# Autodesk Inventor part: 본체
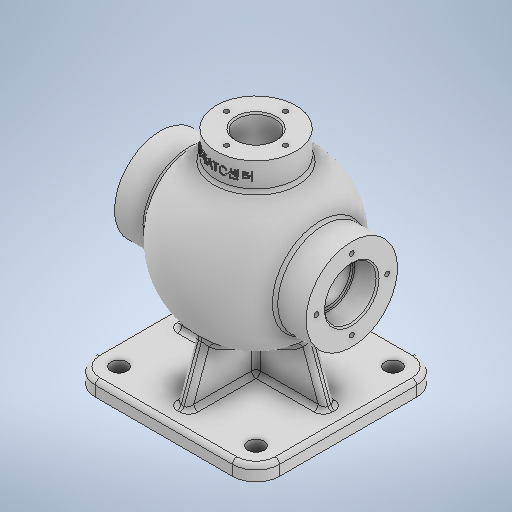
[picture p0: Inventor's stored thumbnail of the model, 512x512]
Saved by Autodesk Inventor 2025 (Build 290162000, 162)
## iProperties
Created: 2024-07
Part Number: 본체
Material: 일반
Document SubType Name: Modeling
Designer: song
Density: 1 g/cm^3
Appearance: 기본값
Mass: 566.359 g
Surface Area: 1179.94 cm^2
Volume: 566.359 cm^3
Author: song
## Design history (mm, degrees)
sketch "스케치1"
  geometry: L1 (-62.5, 62.5)-(62.5, 62.5); L2 (62.5, 62.5)-(62.5, -62.5); L3 (62.5, -62.5)-(-62.5, -62.5); L4 (-62.5, -62.5)-(-62.5, 62.5); L5 (-62.5, 62.5)-(62.5, -62.5); L6 (62.5, 62.5)-(-62.5, -62.5); 1 further point
  constraints: 12 end point, 2 midpoint, 2 parallel, 1 horizontal, 1 perpendicular
  dimensions: "d0" = 125 distance of L2.end L3.end; "d1" = 125 distance of L3.end L1.start
extrude "돌출1" new body sketch "스케치1" distance "d2" = 10; taper "d3" = 0 deg
sketch "스케치2"
  geometry: L1 (-62.5, 0)-(62.5, 0) reference; L2 (-65, 85)-(117.341, 85); L3 (-65, 85)-(-65, 116); L4 (-65, 116)-(-44.215, 116); L5 (65, 85)-(65, 116); L6 (65, 116)-(44.215, 116); L7 (0, 154.371)-(0, -36.93); A1 r 54 centre (0, 85) between (44.215, 116) and (-44.215, 116); 2 further points
  constraints: 12 end point, 3 point on line, 3 vertical, 2 perpendicular, 2 point on circle, 1 centre point, 1 horizontal, 1 midpoint, 1 vertical alignment, 1 other
  dimensions: "d5" = 85 distance between parallel lines of L1 L2; "d6" = 31 distance between parallel lines of L2 L4; "d7" = 65 distance from line of A1.centre L3; "d8" = 31 distance between parallel lines of L2 L6; "d9" = 54 radius of A1
revolve "회전1" sketch "스케치2" stored, may be unused: angle "d10" = 90 deg
node "작업 평면1"
sketch "스케치3"
  geometry: C1 r 27 at (0, 0); 1 further point
  constraints: 1 centre point, 1 coincident
  dimensions: "d12" = 54 diameter of C1
extrude "돌출2" join sketch "스케치3" stored distance "d13" = 10; taper "d14" = 0 deg
sketch "스케치4"
  geometry: L1 (-32.301, 60)-(-50.5, 10); L2 (62.5, 10)-(-62.5, 10) reference; L3 (-62.5, 0)-(-62.5, 10) reference; L4 (-50.5, 10)-(50.5, 10); L5 (50.5, 10)-(32.301, 60); L6 (62.5, 0)-(62.5, 10) reference; L7 (-32.301, 60)-(32.301, 60); A1 r 54 centre (0, 85) between (-44.215, 54) and (-44.215, 116) reference; 1 further point
  constraints: 8 end point, 1 collinear, 1 point on line
  dimensions: "d15" = 12 distance of L2.end L1.end; "d16" = 20 deg angle of L1 L3; "d17" = 12 distance of L2.start L4.end; "d18" = 20 deg angle of L6 L5; "d67" = 50 distance between parallel lines of L2 L7
extrude "돌출3" join sketch "스케치4" stored distance "d19" = 8; taper "d20" = 0 deg
sketch "스케치5"
  geometry: L1 (60, 32.301)-(10, 50.5); L2 (10, -62.5)-(10, 62.5) reference; L3 (10, -50.5)-(60, -32.301); L4 (0, -62.5)-(10, -62.5) reference; L5 (0, 62.5)-(10, 62.5) reference; L6 (60, 32.301)-(60, -32.301); L7 (10, 50.5)-(10, -50.5); A1 r 54 centre (85, 0) between (131.765, 27) and (131.765, -27) reference; 1 further point
  constraints: 8 end point, 2 point on line, 1 collinear, 1 vertical
  dimensions: "d21" = 12 distance of L2.end L1.end; "d22" = 12 distance of L2.start L3.start; "d23" = 20 deg angle of L4 L3; "d24" = 20 deg angle of L5 L1; "d68" = 50 distance between parallel lines of L2 L6
extrude "돌출4" join sketch "스케치5" stored distance "d25" = 8; taper "d26" = 0 deg
sketch "스케치6"
  geometry: L1 (-91.554, 85)-(140.899, 85); L2 (-65, 85)-(-65, 102.5); L3 (-65, 102.5)-(-49, 102.5); L4 (-49, 102.5)-(-49, 100); L5 (49, 100)-(49, 102.5); L6 (49, 102.5)-(65, 102.5); L7 (65, 102.5)-(65, 85); L8 (-65, 54)-(-65, 116) reference; L9 (65, 54)-(65, 116) reference; L10 (0, 180.652)-(0, -35.497); L11 (-49, 100)-(49, 100); A1 r 44 centre (0, 85) between (41.364, 100) and (-41.364, 100); A2 r 54 centre (0, 85) between (37.385, 46.034) and (-37.385, 46.034) reference; 1 further point
  constraints: 18 end point, 6 point on line, 4 perpendicular, 2 collinear, 2 horizontal, 2 point on circle, 2 vertical, 1 centre point, 1 concentric
  dimensions: "d27" = 44 radius of A1; "d28" = 17.5 distance of L2.start L2.end; "d29" = 16 distance between parallel lines of L4 L2; "d30" = 15 distance between parallel lines of L1 L11; "d31" = 16 distance between parallel lines of L9 L5; "d32" = 17.5 distance between parallel lines of L1 L6
revolve "회전2" stored, may be unused: angle "d33" = 90 deg
revolve "회전3" stored, may be unused: angle "d34" = 90 deg
sketch "스케치7"
  geometry: C1 r 27 at (0, 0) reference; 2 further points
  constraints: 1 coincident
hole "구멍1" sketch "스케치7" at (0, 0) diameter "d35" = 26; stored, may be unused: countersink angle "d39" = 90 deg, drill point angle "d41" = 0 deg; dims "d36" = 6, "d37" = 4, "d38" = 2, "d40" = 8
sketch "스케치8"
  geometry: C1 r 31 at (0, 0) reference; 2 further points
  constraints: 1 vertical alignment
  dimensions: "d49" = 24 distance of C1.centre point (0, 24)
hole "구멍2" sketch "스케치8" at (0, 24) diameter "d42" = 3.242; stored, may be unused: countersink angle "d46" = 90 deg, drill point angle "d48" = 120 deg; dims "d43" = 12, "d44" = 4, "d45" = 2, "d47" = 15
sketch "스케치9"
  geometry: 2 further points
  constraints: 1 vertical alignment
  dimensions: "d60" = 20 distance of point (0, -20) point (0, 0)
hole "구멍3" sketch "스케치9" at (0, -20) diameter "d53" = 3.242; stored, may be unused: countersink angle "d57" = 90 deg, drill point angle "d59" = 120 deg; dims "d54" = 9, "d55" = 4, "d56" = 2, "d58" = 11
fillet "모깎기1" dims "d65" = 3
fillet "모깎기3" dims "d69" = 3
fillet "모깎기4" dims "d70" = 3
fillet "모깎기5" dims "d79" = 16
sketch "스케치13"
  geometry: A1 r 16 centre (-46.5, 46.5) between (-46.5, 62.5) and (-62.5, 46.5) reference; A2 r 16 centre (46.5, 46.5) between (62.5, 46.5) and (46.5, 62.5) reference; A3 r 16 centre (-46.5, -46.5) between (-62.5, -46.5) and (-46.5, -62.5) reference; A4 r 16 centre (46.5, -46.5) between (46.5, -62.5) and (62.5, -46.5) reference; 5 further points
  constraints: 4 coincident
hole "구멍5" sketch "스케치13" at (-46.5, 46.5), (46.5, 46.5), (-46.5, -46.5), (46.5, -46.5) diameter "d80" = 11; stored, may be unused: countersink angle "d84" = 90 deg, drill point angle "d86" = 0 deg; dims "d81" = 6, "d82" = 4, "d83" = 2, "d85" = 8
node "작업 평면3"
sketch "스케치14"
  geometry: L1 (27, 150)-(-27, 150) reference; 2 further points
  constraints: 1 vertical alignment, 1 other
  dimensions: "d88" = 9 distance from line of point (0, 141) L1
feature "엠보싱1" sketch "스케치14" dims "d0" = 125, "d1" = 125, "d89" = 0.5, "d90" = 0
chamfer "모따기1" distance "d95" = 1; stored, may be unused: second distance "d96" = 2, angle "d97" = 45 deg
fillet "모깎기6" dims "d98" = 0.6
fillet "모깎기7" dims "d99" = 3
node "솔리드1"
pattern_circular "원형 패턴1" dims angle "d51" = 360 deg
mirror "미러1"
pattern_circular "원형 패턴2" dims angle "d62" = 360 deg
feature "A9D066F2-1C7D-4E18-AEED-F7BC21143FA4" dims "d80" = 11, "d81" = 6, "d82" = 4, "d83" = 2, "d84" = 90 deg, "d85" = 8, "d86" = 0
other parameters: "d4" = 54, "d87" = 27
